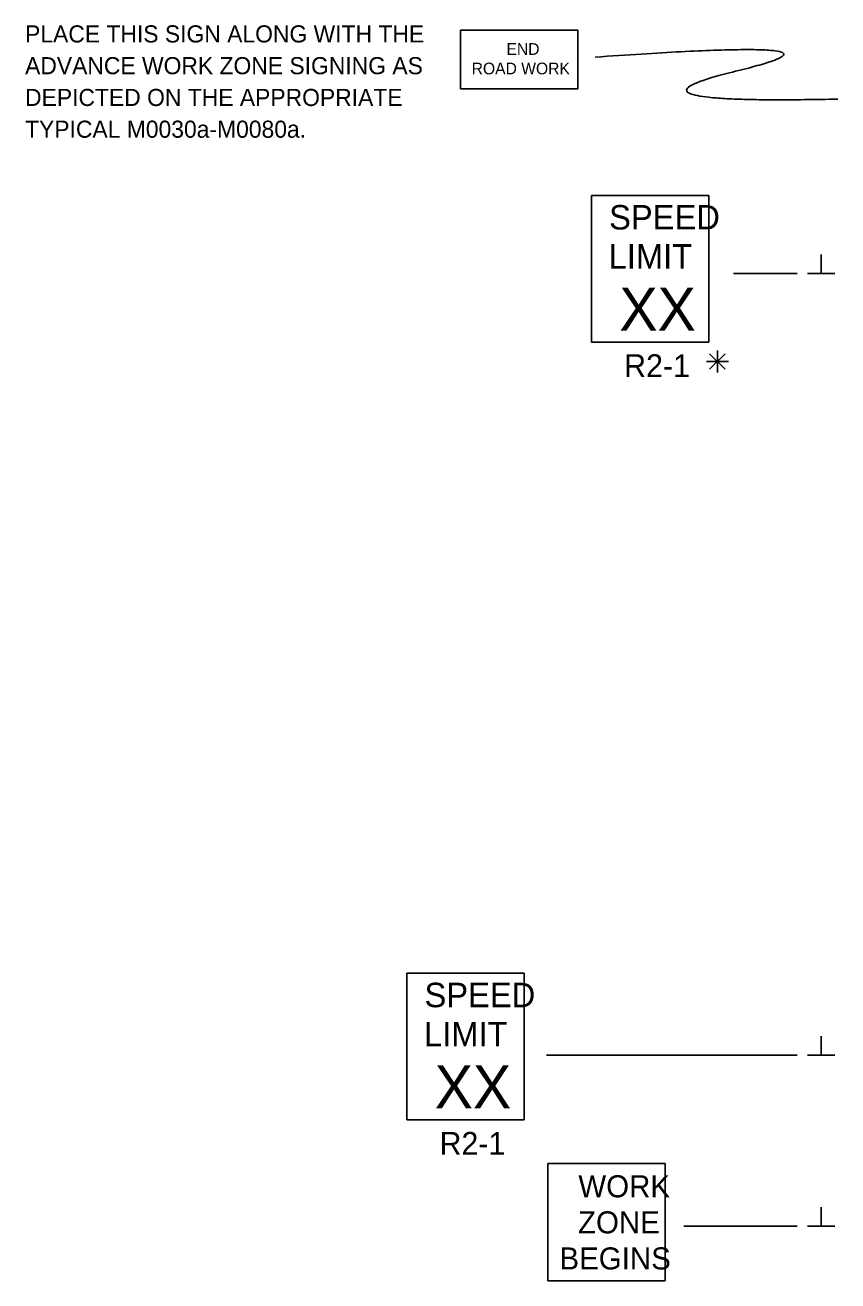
# Model space of a CAD drawing. Extents: x 16739 to 18475, y 5720 to 6924.
# Drawn here: x 16759 to 17092, y 6395 to 6909 of the extents above; entities that cross this region are included whole.
import ezdxf

# ---------------------------------------------------------------- set-up
doc = ezdxf.new("R2010")
doc.units = 0
doc.layers.add('TRAFFIC_SIGNS_PR', color=7, linetype='Continuous')
doc.layers.add('TYPICAL_TEXT_DIMEN_PR', color=7, linetype='Continuous')

msp = doc.modelspace()

# ---------------------------------------------------------------- linework, layer by layer
at = {"layer": 'TRAFFIC_SIGNS_PR'}
for p, q in [((16991.15, 6839.33), (17039.15, 6839.33)), ((16991.15, 6779.33), (16991.15, 6839.33)), ((17039.15, 6779.33), (17039.15, 6839.33)), ((16991.15, 6779.33), (17039.15, 6779.33)), ((16915.59, 6521), (16963.59, 6521)), ((16915.59, 6461), (16915.59, 6521)), ((16963.59, 6461), (16963.59, 6521)), ((16915.59, 6461), (16963.59, 6461)), ((16973.26, 6395.06), (16973.26, 6443.06)), ((16973.26, 6443.06), (17021.26, 6443.06)), ((17021.26, 6395.06), (17021.26, 6443.06)), ((16973.26, 6395.06), (17021.26, 6395.06))]:
    msp.add_line(p, q, dxfattribs=at)
msp.add_lwpolyline([(16937.58, 6882.98), (16985.58, 6882.98), (16985.58, 6906.98), (16937.58, 6906.98)], close=True, dxfattribs=at)
msp.add_open_spline([(16992.7, 6895.96), (17107.93, 6904.19), (16994.02, 6876.61), (17091.96, 6878.78)], degree=2, dxfattribs=at)
at = {"layer": 'TYPICAL_TEXT_DIMEN_PR'}
for p, q in [((17085.12, 6807.33), (17085.12, 6815.12)), ((17049.25, 6807.33), (17075.25, 6807.33)), ((17079.5, 6807.33), (17090.75, 6807.33)), ((17042.68, 6771.38), (17042.68, 6775.83)), ((17042.68, 6771.38), (17038.14, 6771.38)), ((17039.49, 6774.56), (17045.86, 6768.19)), ((17045.86, 6774.56), (17039.49, 6768.19)), ((17042.68, 6771.38), (17045.86, 6771.38)), ((17042.68, 6771.38), (17047.15, 6771.38)), ((17042.68, 6771.38), (17042.68, 6766.88)), ((17085.12, 6487.44), (17085.12, 6495.22)), ((16972.74, 6487.44), (17075.25, 6487.44)), ((17079.5, 6487.44), (17090.75, 6487.44)), ((17085.12, 6417.44), (17085.12, 6425.22)), ((17028.93, 6417.44), (17075.25, 6417.44)), ((17079.5, 6417.44), (17090.75, 6417.44))]:
    msp.add_line(p, q, dxfattribs=at)

# ---------------------------------------------------------------- texts
at = {"layer": 'TRAFFIC_SIGNS_PR'}
for s, height, p in [('PLACE THIS SIGN ALONG WITH THE', 7, (16759.34, 6901.96)), ('END', 4.789, (16956.33, 6896.89)), ('ADVANCE WORK ZONE SIGNING AS', 7, (16759.34, 6888.96)), ('ROAD WORK', 4.789, (16942.09, 6888.91)), ('DEPICTED ON THE APPROPRIATE', 7, (16759.34, 6875.96)), ('TYPICAL M0030a-M0080a.', 7, (16759.34, 6862.96)), ('SPEED', 10, (16998.35, 6825.41)), ('LIMIT', 10, (16998.15, 6809.41)), ('XX', 17.538, (17002.54, 6784.03)), ('R2-1', 9.3, (17004.49, 6765.03)), ('SPEED', 10, (16922.8, 6507.08)), ('LIMIT', 10, (16922.6, 6491.08)), ('XX', 17.538, (16926.98, 6465.7)), ('R2-1', 9.3, (16928.94, 6446.7)), ('WORK', 9.021, (16985.76, 6429.26)), ('ZONE', 9.021, (16985.61, 6414.5)), ('BEGINS', 9.021, (16978.02, 6399.74))]:
    msp.add_text(s, height=height, dxfattribs=at).set_placement(p)

doc.saveas('drawing.dxf')
